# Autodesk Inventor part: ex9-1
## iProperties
Author: Administrator
Created: 2001-03
Part Number: ex9-1
Material: Default
Document SubType Name: Modeling
Designer: Administrator
Control State: 0
Master: False
Checked Out: False
PropertySet Name: Design Tracking Control
Shininess: 20.0
PropertySet Name: _Private Model Information
Density: 0.0
Volumn: 0.0
Area: 0.0
PropertySet Name: Model Information
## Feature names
1. Extrusion1
